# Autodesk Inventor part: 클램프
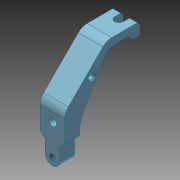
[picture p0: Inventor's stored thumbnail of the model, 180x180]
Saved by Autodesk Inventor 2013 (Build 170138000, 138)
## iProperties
Created: 2023-11
Part Number: 클램프
Material: 강철, 합금
Document SubType Name: Modeling
Designer: mdu-01
Density: 1 g/cm^3
Author: mdu-01
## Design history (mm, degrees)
sketch "스케치1"
  geometry: L1 (0, 0)-(37.858, 0); L2 (44.929, -2.929)-(73.071, -31.071); L3 (76, -38.142)-(76, -59); L4 (74, -61)-(67, -61); L5 (66, -60)-(66, -56); L6 (67, -55)-(69, -55); L7 (70, -54)-(70, -40.868); L8 (65, -32.207)-(36.962, -16.019); L9 (21.962, -12)-(0, -12); L10 (0, -12)-(0, 0); L11 (66, -49.956)-(66, -66.044) reference; L12 (76, -59)-(74, -61); L13 (29.771, -17)-(32.23, -17) reference; L14 (31, -17)-(31, 0); L15 (6, -17.549)-(6, 0); C1 r 2 at (56, -22); A1 r 1 centre (67, -56) between (67, -55) and (66, -56); A2 r 1 centre (67, -60) between (66, -60) and (67, -61); A3 r 1 centre (69, -54) between (69, -55) and (70, -54); A4 r 10 centre (60, -40.868) between (70, -40.868) and (65, -32.207); A5 r 30 centre (21.962, -42) between (36.962, -16.019) and (21.962, -12); A6 r 10 centre (37.858, -10) between (44.929, -2.929) and (37.858, 0); A7 r 10 centre (66, -38.142) between (76, -38.142) and (73.071, -31.071); A8 r 6 centre (6, -17.549) between (10, -13.076) and (2, -13.076) reference; 4 further points
  constraints: 26 end point, 16 point on circle, 14 tangent, 9 centre point, 8 point on line, 5 parallel, 3 midpoint, 3 perpendicular, 2 horizontal, 1 equal radius, 4 other
  dimensions: "d0" = 12 distance between parallel lines of L1 L9; "d3" = 6 distance between parallel lines of L7 L3; "d4" = 10 distance between parallel lines of L5 L3; "d6" = 150 deg angle of L9 L8; "d7" = 30 distance from line of point (30, -12) L10; "d8" = 45 deg angle of L2 L1; "d9" = 42 distance of L1.start point (42, 0); "d10" = 6 distance between parallel lines of L6 L4; "d11" = 4 diameter of C1; "d12" = 22 distance from line of C1.centre L1; "d13" = 56 distance from line of C1.centre L10; "d14" = 1 radius of A1; "d15" = 61 distance between parallel lines of L4 L1 (derived); "d16" = 1 radius of A3; "d17" = 2 distance of L3.end point (76, -61); "d18" = 2 distance of L4.start point (76, -61) (= d17); "d19" = 10 radius of A4; "d20" = 30 radius of A5; "d21" = 10 radius of A6; "d22" = 10 radius of A7; "d23" = 6 distance between parallel lines of L15 L10 (derived); "d24" = 25 distance between parallel lines of L14 L15 (derived)
extrude "돌출1" new body sketch "스케치1" stored distance "d25" = 20; taper "d26" = 0 deg
sketch "스케치2"
  geometry: L1 (0, -21.962)-(20, -21.962) reference; L2 (0, -21.962)-(0, -1.962); L3 (0, -1.962)-(4, -5.962); L4 (4, -5.962)-(4, -21.962); L5 (10, -21.962)-(10, 6.53); L6 (20, -21.962)-(20, -1.962); L7 (20, -1.962)-(16, -5.962); L8 (16, -5.962)-(16, -21.962); L9 (0, -21.962)-(4, -21.962); L10 (16, -21.962)-(20, -21.962)
  constraints: 18 end point, 3 symmetric about line, 2 collinear, 2 perpendicular, 1 point on line, 1 vertical
  dimensions: "d27" = 45 deg angle of L2 L3; "d28" = 12 distance between parallel lines of L8 L4; "d30" = 20 distance from line of L2.end L1
extrude "돌출2" cut sketch "스케치2" stored distance "d31" = 20; taper "d32" = 0 deg
fillet "모깎기1"
chamfer "모따기1" distance "d33" = 1; stored, may be unused: second distance "d34" = 2, angle "d35" = 45 deg
hole "구멍1" diameter "d38" = 4.917; stored, may be unused: countersink angle "d42" = 90 deg, drill point angle "d44" = 118 deg; dims "d39" = 6, "d40" = 7, "d41" = 4, "d43" = 8, "d47" = 10, "d48" = 10
sketch "스케치3"
  geometry: C1 r 2.75 at (10, -6.858) reference; 1 further point
hole "구멍2" sketch "스케치3" at (10, -6.858) diameter "d45" = 4; stored, may be unused: countersink angle "d51" = 90 deg, drill point angle "d53" = 118 deg; dims "d46" = 6, "d49" = 6.5, "d50" = 8, "d52" = 8
sketch "스케치4"
  geometry: L1 (20, 22.858)-(0, 22.858) reference; L2 (20, 15.858)-(0, 15.858) reference; L3 (6.5, 15.858)-(6.5, 22.858); L4 (13.5, 15.858)-(13.5, 22.858); C1 r 2.5 at (10, 19.858) reference; A1 r 3.5 centre (10, 15.858) between (6.5, 15.858) and (13.5, 15.858); 1 further point
  constraints: 4 end point, 3 point on line, 2 perpendicular, 2 point on circle, 2 tangent, 1 centre point, 1 midpoint
  dimensions: "d57" = 7 diameter of A1
extrude "돌출3" cut sketch "스케치4" stored distance "d55" = 20; taper "d56" = 0 deg
node "솔리드1"
node "참조1"
node "참조2"
node "참조3"
node "참조4"
